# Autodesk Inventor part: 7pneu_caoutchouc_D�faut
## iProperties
Created: 2011-01
Part Number: 7pneu_caoutchouc_D�faut
Document SubType Name: Modeling
Designer: eric
Density: 1 g/cm^3
Mass: 1652.98 g
Surface Area: 1753.05 cm^2
Volume: 1652.98 cm^3
Author: eric
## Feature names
1. Base1
